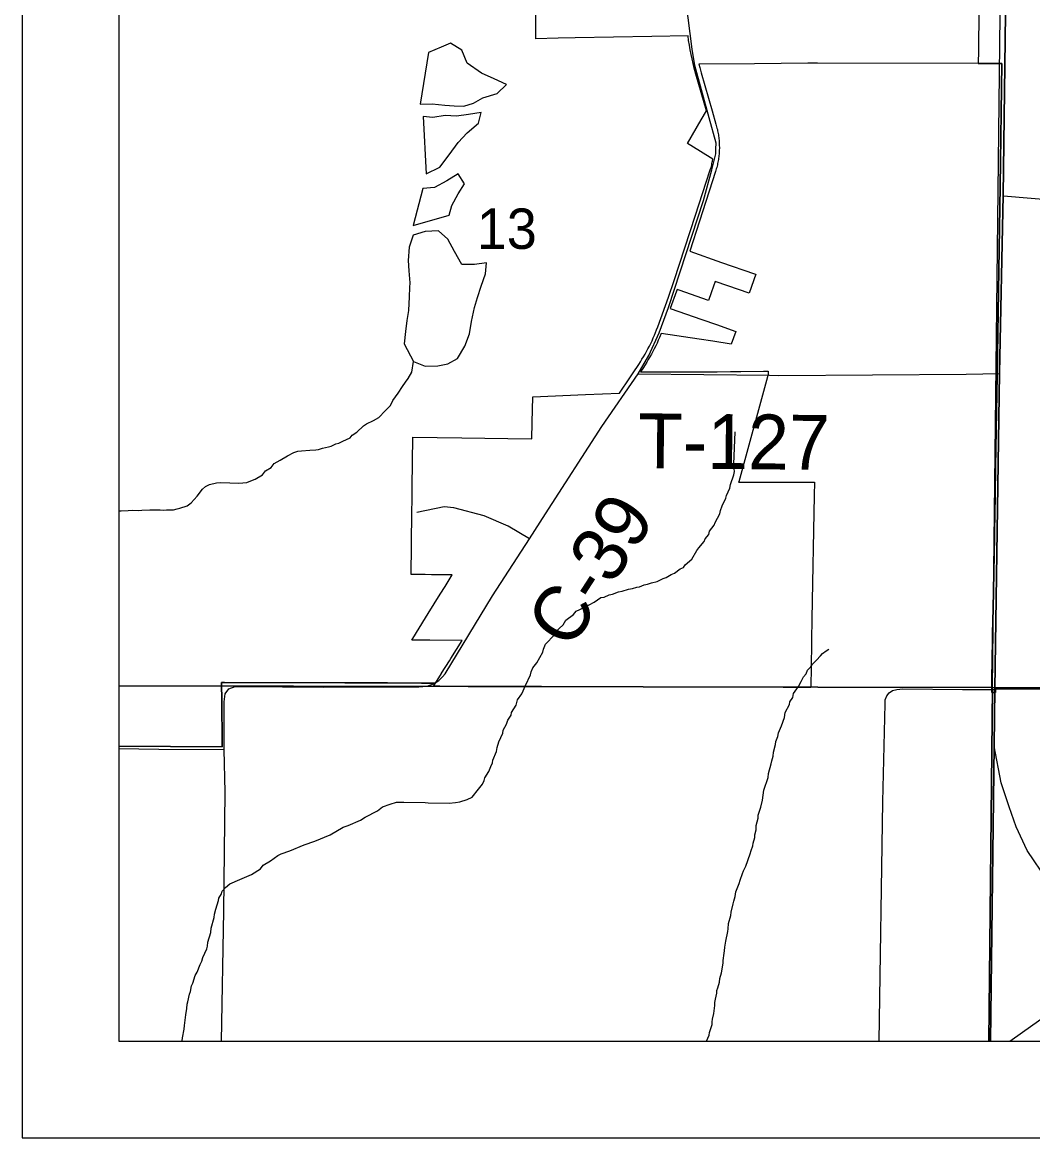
# Model space of a CAD drawing. Extents: x 0 to 34, y 0 to 22.
# Drawn here: x 2 to 3.047, y 14 to 15.156 of the extents above; entities that cross this region are included whole.
import ezdxf

# ---------------------------------------------------------------- set-up
doc = ezdxf.new("R2010")
doc.units = 0
for name, color, linetype in [('Default', 7, 'Continuous'), ('GM_X_City_Street', 7, 'Continuous'), ('GM_X_County_Road', 7, 'Continuous'), ('GM_X_County_Road_Text', 7, 'Continuous'), ('GM_X_Minor_Lake', 7, 'Continuous'), ('GM_X_Minor_River', 7, 'Continuous'), ('GM_X_Section', 7, 'Continuous'), ('GM_X_Section_Text', 7, 'Continuous'), ('GM_X_State_Route', 7, 'Continuous'), ('GM_X_Township_Road', 7, 'Continuous'), ('GM_X_Township_Road_Text', 7, 'Continuous'), ('SC_Shading3', 7, 'Continuous'), ('SH_Data', 7, 'Continuous')]:
    doc.layers.add(name, color=color, linetype=linetype)

msp = doc.modelspace()

# ---------------------------------------------------------------- linework, layer by layer
at = {"layer": 'Default'}
for points in [[(2.1, 15.4427), (2.1, 14.4681), (3.0051, 14.4664), (3.0163, 15.4353)], [(2.1, 14.4681), (2.1, 14.1), (3.0014, 14.1), (3.0051, 14.4664)], [(3.0014, 14.1), (3.9062, 14.1), (3.8976, 14.2918), (3.8947, 14.4604), (3.0051, 14.4664)]]:
    msp.add_lwpolyline(points, close=True, dxfattribs=at)
at = {"layer": 'GM_X_City_Street'}
for p, q in [((2.978, 14.791), (3.0125, 14.7916)), ((2.9742, 14.4643), (3.0076, 14.4645))]:
    msp.add_line(p, q, dxfattribs=at)
for points in [[(3.0164, 14.9758), (3.1269, 14.9664)], [(2.8876, 14.1), (2.8916, 14.3479), (2.8938, 14.4496), (2.8941, 14.4537), (2.8956, 14.4577), (2.898, 14.4609), (2.9014, 14.4634), (2.906, 14.4645), (2.9121, 14.4649), (2.9742, 14.4643)]]:
    msp.add_lwpolyline(points, dxfattribs=at)
at = {"layer": 'GM_X_County_Road'}
for points in [[(3.0165, 14.9818), (3.0224, 15.4329), (3.0236, 15.5763), (3.0235, 15.5833)], [(2.4352, 14.4775), (2.4381, 14.4807), (2.4873, 14.5614), (2.5254, 14.6205), (2.542, 14.6464), (2.6005, 14.7367), (2.6379, 14.7912), (2.6492, 14.8104), (2.6599, 14.8337), (2.6693, 14.8602), (2.7057, 14.9708), (2.7143, 15.0026), (2.7184, 15.0194), (2.7185, 15.0244), (2.7188, 15.0303), (2.7117, 15.0566), (2.6967, 15.1109), (2.6941, 15.1277), (2.6856, 15.193)], [(3.0076, 14.4645), (3.0125, 14.7916), (3.0164, 14.9758), (3.0165, 14.9818)], [(2.2064, 14.1), (2.2087, 14.2347), (2.2102, 14.358), (2.2093, 14.4023), (2.2091, 14.4514), (2.2101, 14.4598), (2.214, 14.465), (2.2205, 14.4674), (2.2268, 14.4674), (2.3125, 14.4668), (2.4108, 14.467), (2.4194, 14.4677), (2.4259, 14.4702), (2.4314, 14.4735), (2.4352, 14.4775)], [(3.1314, 14.1866), (3.0969, 14.2252), (3.062, 14.2664), (3.0411, 14.2975), (3.0297, 14.3219), (3.0224, 14.3428), (3.0142, 14.3675), (3.0069, 14.4055), (3.0076, 14.4645)]]:
    msp.add_lwpolyline(points, dxfattribs=at)
at = {"layer": 'GM_X_Minor_Lake'}
for points in [[(2.4122, 15.0708), (2.4247, 15.071), (2.4376, 15.0696), (2.4475, 15.069), (2.4574, 15.0688), (2.4674, 15.0717), (2.477, 15.0772), (2.4919, 15.0818), (2.5016, 15.0911), (2.4888, 15.0971), (2.4756, 15.1027), (2.461, 15.1132), (2.4555, 15.1266), (2.4435, 15.1341), (2.4339, 15.1297), (2.4209, 15.1243)], [(2.4209, 15.1243), (2.4122, 15.0708)], [(2.4183, 14.9985), (2.4325, 15.0055), (2.4423, 15.0182), (2.4517, 15.0309), (2.461, 15.041), (2.4727, 15.051), (2.4755, 15.062), (2.4622, 15.06), (2.45, 15.0583), (2.4382, 15.0589), (2.4252, 15.0569), (2.4153, 15.0579)], [(2.4153, 15.0579), (2.4183, 14.9985)], [(2.4422, 14.9559), (2.445, 14.9657), (2.4514, 14.9777), (2.4581, 14.9882), (2.4514, 14.9986), (2.4398, 14.9913), (2.4271, 14.9843), (2.4149, 14.9834)], [(2.4149, 14.9834), (2.405, 14.9452), (2.4422, 14.9559)], [(2.4052, 14.8042), (2.4173, 14.7994), (2.4306, 14.7995), (2.4409, 14.8016), (2.4509, 14.8071), (2.4584, 14.8199), (2.4633, 14.8327), (2.4654, 14.8456), (2.4684, 14.86), (2.4716, 14.8706), (2.4753, 14.8823), (2.4798, 14.8951), (2.4808, 14.9065), (2.4685, 14.9048), (2.4552, 14.9047), (2.4479, 14.9181), (2.4409, 14.9308), (2.4312, 14.9394), (2.4175, 14.9389), (2.4048, 14.9349), (2.4008, 14.9225), (2.3997, 14.9088), (2.4006, 14.8982), (2.4015, 14.8856)], [(2.4015, 14.8856), (2.401, 14.8807), (2.4009, 14.8712), (2.4002, 14.8571), (2.3984, 14.8465), (2.3971, 14.8351), (2.3957, 14.8226), (2.4052, 14.8042)]]:
    msp.add_lwpolyline(points, dxfattribs=at)
at = {"layer": 'GM_X_Minor_River'}
for points in [[(2.2892, 14.7117), (2.298, 14.7122), (2.3041, 14.7128), (2.3068, 14.7131), (2.311, 14.7142), (2.3172, 14.7159), (2.3199, 14.7166), (2.3249, 14.7188), (2.3279, 14.7195), (2.3322, 14.7217), (2.3395, 14.7249), (2.3419, 14.7279), (2.3465, 14.7308), (2.3536, 14.7375), (2.3567, 14.7397), (2.364, 14.743), (2.3694, 14.7463), (2.3761, 14.753), (2.3816, 14.7586), (2.384, 14.7638), (2.3895, 14.7713), (2.3939, 14.7781), (2.3971, 14.7829), (2.3998, 14.7867), (2.4034, 14.7931), (2.4052, 14.8042)], [(2.4921, 14.4044), (2.4938, 14.41), (2.4978, 14.4191), (2.4983, 14.4221), (2.5015, 14.4285), (2.5031, 14.4327), (2.5063, 14.4379), (2.5068, 14.4406), (2.5115, 14.4481), (2.5132, 14.4538), (2.5176, 14.4597), (2.5212, 14.4684), (2.5265, 14.4797), (2.5273, 14.4827), (2.5289, 14.4869), (2.5329, 14.4921), (2.5393, 14.503), (2.5401, 14.506), (2.5421, 14.5113), (2.5512, 14.521), (2.5524, 14.524), (2.5602, 14.5315), (2.563, 14.536), (2.5711, 14.5422), (2.5739, 14.5456), (2.582, 14.5492), (2.5924, 14.5547), (2.5994, 14.5595), (2.6029, 14.5601), (2.6079, 14.5623), (2.6113, 14.563), (2.6175, 14.5655), (2.6213, 14.5662), (2.6279, 14.5683), (2.6321, 14.569), (2.6367, 14.5704), (2.6394, 14.5707), (2.6444, 14.5728), (2.6478, 14.5735), (2.652, 14.5749), (2.6578, 14.5763), (2.664, 14.5792), (2.667, 14.5803), (2.6721, 14.5836), (2.6756, 14.585), (2.6814, 14.5895), (2.6849, 14.5909), (2.6868, 14.5935), (2.6935, 14.5995), (2.6987, 14.6085), (2.701, 14.6111), (2.7065, 14.6178), (2.7073, 14.6204), (2.7113, 14.6249), (2.7121, 14.6283), (2.7169, 14.6347), (2.7177, 14.6373), (2.7225, 14.6464), (2.7234, 14.6498), (2.725, 14.6547), (2.729, 14.6626), (2.7295, 14.6652), (2.7331, 14.6728), (2.7336, 14.6766), (2.7373, 14.6868), (2.7377, 14.6902), (2.7374, 14.6928), (2.7372, 14.6978), (2.7384, 14.7313)], [(2.1, 14.6496), (2.1024, 14.6495), (2.1096, 14.6497), (2.1138, 14.65), (2.1199, 14.6499), (2.1237, 14.6502), (2.1321, 14.6503), (2.1356, 14.6506), (2.1428, 14.6505), (2.1466, 14.65), (2.1493, 14.6503), (2.1565, 14.6505), (2.1604, 14.6516), (2.1631, 14.6523), (2.1707, 14.6547), (2.175, 14.6577), (2.1813, 14.6648), (2.1868, 14.6719), (2.1899, 14.6748), (2.1938, 14.6767), (2.2011, 14.6784), (2.2057, 14.6787), (2.2243, 14.6782), (2.2327, 14.6788), (2.2385, 14.6813), (2.2412, 14.6824), (2.2489, 14.6867), (2.2521, 14.6909), (2.2579, 14.6945), (2.2611, 14.6986), (2.2673, 14.7019), (2.2746, 14.7063), (2.2812, 14.71), (2.2854, 14.7114), (2.2892, 14.7117)], [(2.7391, 14.2548), (2.7427, 14.2635), (2.7436, 14.2669), (2.746, 14.2737), (2.7473, 14.2763), (2.7497, 14.2812), (2.7542, 14.294), (2.755, 14.2974), (2.7567, 14.3024), (2.7571, 14.305), (2.7588, 14.3111), (2.7589, 14.3137), (2.7602, 14.319), (2.7603, 14.3236), (2.7624, 14.3312), (2.7625, 14.3342), (2.765, 14.3425), (2.7667, 14.3497), (2.7681, 14.36), (2.7726, 14.3732), (2.7731, 14.3774), (2.7757, 14.3872), (2.7765, 14.3903), (2.7778, 14.3952), (2.7783, 14.3994), (2.7804, 14.4073), (2.7808, 14.4103), (2.7829, 14.4156), (2.7834, 14.4194), (2.7866, 14.4266), (2.7895, 14.4353), (2.7904, 14.4406), (2.7948, 14.4489), (2.7952, 14.4515), (2.7984, 14.456), (2.7989, 14.4602), (2.804, 14.4673), (2.8068, 14.4726), (2.8092, 14.4774), (2.812, 14.4804), (2.8136, 14.4842), (2.8171, 14.4879), (2.8187, 14.4905), (2.8227, 14.4946), (2.827, 14.4991), (2.8289, 14.5017), (2.8328, 14.5043), (2.8355, 14.5061)], [(2.1655, 14.1), (2.1656, 14.1002), (2.166, 14.1033), (2.1678, 14.1124), (2.1679, 14.1162), (2.1689, 14.1245), (2.1693, 14.1272), (2.1706, 14.134), (2.1707, 14.1382), (2.1716, 14.1409), (2.1733, 14.1488), (2.1741, 14.1515), (2.1754, 14.1575), (2.1766, 14.1602), (2.1791, 14.1681), (2.1811, 14.1715), (2.1844, 14.1794), (2.186, 14.1828), (2.1872, 14.1866), (2.1913, 14.1956), (2.1917, 14.1983), (2.1922, 14.2025), (2.1952, 14.2127), (2.1956, 14.2169), (2.1986, 14.2282), (2.1991, 14.2316), (2.2004, 14.2369), (2.2032, 14.2456), (2.2037, 14.2483), (2.2065, 14.2528), (2.2069, 14.2554), (2.2105, 14.2592), (2.2151, 14.2629), (2.2255, 14.2676), (2.2375, 14.2726), (2.2468, 14.2785), (2.2496, 14.2822), (2.2573, 14.287), (2.2647, 14.2925), (2.2682, 14.294), (2.277, 14.2972), (2.292, 14.3033), (2.3032, 14.3072), (2.319, 14.3137), (2.3325, 14.3217), (2.3375, 14.3235), (2.3503, 14.3289), (2.3553, 14.3319), (2.368, 14.3388), (2.3731, 14.3429), (2.3812, 14.3457), (2.3877, 14.3475), (2.3953, 14.3477), (2.4174, 14.3471), (2.4205, 14.347), (2.4422, 14.3465), (2.4487, 14.3471), (2.4533, 14.3478), (2.461, 14.3503), (2.466, 14.3528), (2.4727, 14.361), (2.4766, 14.3663), (2.4786, 14.37), (2.4791, 14.3727), (2.4835, 14.3794), (2.4855, 14.3847), (2.4871, 14.3885), (2.4876, 14.3911), (2.4912, 14.4002), (2.4921, 14.4044)], [(2.709, 14.1), (2.7116, 14.1061), (2.7121, 14.1091), (2.7146, 14.1174), (2.7146, 14.1201), (2.7151, 14.1228), (2.7164, 14.1285), (2.7173, 14.1368), (2.7174, 14.1399), (2.7183, 14.1436), (2.7196, 14.1497), (2.7197, 14.1524), (2.7205, 14.1554), (2.7222, 14.1611), (2.7226, 14.1649), (2.7243, 14.1709), (2.7261, 14.1808), (2.7262, 14.1835), (2.7271, 14.1911), (2.7276, 14.1937), (2.7277, 14.1975), (2.729, 14.2036), (2.7308, 14.2135), (2.7312, 14.2165), (2.7317, 14.2218), (2.7342, 14.2301), (2.7343, 14.2336), (2.7365, 14.2423), (2.7373, 14.2449), (2.7386, 14.2498), (2.7391, 14.2548)]]:
    msp.add_lwpolyline(points, dxfattribs=at)
at = {"layer": 'GM_X_Section'}
msp.add_lwpolyline([(3.0168, 15.4789), (4.0112, 15.46), (4.0068, 14.8003), (3.9922, 14.7706), (3.9618, 14.7034), (3.9313, 14.6142), (3.9035, 14.5261), (3.8947, 14.4604), (3.0051, 14.4664), (3.0163, 15.4353)], close=True, dxfattribs=at)
at = {"layer": 'GM_X_State_Route'}
for points in [[(2.1, 15.7155), (2.1, 14.4056), (2.2071, 14.4051), (2.2071, 14.4067), (2.2067, 14.4549), (2.2065, 14.4684), (2.2065, 14.4717), (2.2094, 14.4717), (2.3341, 14.4713), (2.3784, 14.4711), (2.4136, 14.471), (2.4171, 14.471), (2.428, 14.4709), (2.4343, 14.481), (2.4344, 14.4812), (2.4426, 14.4941), (2.444, 14.4964), (2.4556, 14.5152), (2.4222, 14.5153), (2.4035, 14.5154), (2.4085, 14.5235), (2.4205, 14.5429), (2.433, 14.563), (2.438, 14.5712), (2.4453, 14.583), (2.4423, 14.5831), (2.424, 14.5833), (2.4175, 14.5834), (2.4028, 14.5836), (2.4032, 14.6135), (2.4037, 14.6499), (2.4038, 14.6593), (2.404, 14.6741), (2.4047, 14.7256), (2.4299, 14.7253), (2.4552, 14.7249), (2.5029, 14.7243), (2.5278, 14.724), (2.5282, 14.741), (2.5288, 14.7677), (2.5834, 14.7699), (2.6186, 14.7713), (2.6293, 14.7873), (2.6315, 14.7905), (2.6327, 14.7924), (2.6387, 14.8012), (2.6404, 14.8038), (2.642, 14.8064), (2.6437, 14.8091), (2.6452, 14.8117), (2.6467, 14.8144), (2.6482, 14.8171), (2.6497, 14.8201), (2.6511, 14.8229), (2.6524, 14.8257), (2.6537, 14.8285), (2.6549, 14.8313), (2.6561, 14.8342), (2.6572, 14.8371), (2.6584, 14.8402), (2.6694, 14.8707), (2.6755, 14.8879), (2.6976, 14.9558), (2.7048, 14.9781), (2.7128, 15.0028), (2.7136, 15.0053), (2.7139, 15.0066), (2.7142, 15.0079), (2.7145, 15.0092), (2.7148, 15.0105), (2.7151, 15.0118), (2.7155, 15.0139), (2.6927, 15.0278), (2.6891, 15.03), (2.7034, 15.0545), (2.7088, 15.0637), (2.6979, 15.1017), (2.6962, 15.1082), (2.695, 15.1129), (2.6939, 15.1176), (2.6929, 15.1223), (2.6919, 15.1271), (2.6911, 15.1319), (2.6903, 15.1366), (2.6897, 15.1414), (2.6522, 15.1408), (2.5728, 15.1393), (2.5553, 15.139), (2.532, 15.1386), (2.5319, 15.1867)], [(2.9911, 15.1676), (2.9905, 15.1263), (2.9903, 15.113), (3.0086, 15.113), (3.0149, 15.113), (3.013, 14.9859), (3.0101, 14.7895), (3.0084, 14.695), (3.0079, 14.6653), (3.0072, 14.6277), (3.0071, 14.6225), (3.0065, 14.5851), (3.0058, 14.5482), (3.0053, 14.5225), (3.0052, 14.5141), (3.0049, 14.4971), (3.0045, 14.4737), (3.0044, 14.4688), (3.0043, 14.4613), (3.0081, 14.4612), (3.0081, 14.4614), (3.0081, 14.465), (3.0085, 14.465), (3.0119, 14.465), (3.0166, 14.465), (3.0176, 14.465), (3.0299, 14.465), (3.0327, 14.465), (3.0419, 14.4649), (3.046, 14.4649), (3.0554, 14.4649)]]:
    msp.add_lwpolyline(points, dxfattribs=at)
at = {"layer": 'GM_X_Township_Road'}
msp.add_line((2.6379, 14.7912), (2.774, 14.7899), dxfattribs=at)
for points in [[(2.1, 17.494), (2.1, 14.1), (3.0031, 14.1), (3.0067, 14.4061), (3.0074, 14.465), (3.0123, 14.7921), (3.0162, 14.9764), (3.0222, 15.4334), (3.0233, 15.5768), (3.0198, 16.3586)], [(3.0198, 16.3586), (3.0233, 15.5768), (3.0222, 15.4334), (3.0162, 14.9764), (3.0123, 14.7921), (3.0074, 14.465), (3.0067, 14.4061), (3.0031, 14.1), (3.9251, 14.1)], [(2.774, 14.7899), (2.7837, 14.7898), (2.978, 14.791)], [(2.5254, 14.6205), (2.5032, 14.6335), (2.4784, 14.6441), (2.4471, 14.6526), (2.4369, 14.6536), (2.4086, 14.6476)], [(2.1, 14.4031), (2.1413, 14.4024), (2.2093, 14.4023)], [(3.0232, 14.1), (3.0363, 14.1092), (3.0671, 14.1311), (3.0828, 14.1429), (3.1007, 14.1583), (3.1314, 14.1866)]]:
    msp.add_lwpolyline(points, dxfattribs=at)
at = {"layer": 'SC_Shading3'}
msp.add_lwpolyline([(3.0554, 14.4649), (3.046, 14.4649), (3.0431, 14.4649), (3.0419, 14.4649), (3.0327, 14.465), (3.0299, 14.465), (3.0176, 14.465), (3.0166, 14.465), (3.0119, 14.465), (3.0085, 14.465), (3.0081, 14.465), (3.0081, 14.4614), (3.0081, 14.4612), (3.0043, 14.4613), (3.0044, 14.4688), (3.0045, 14.4737), (3.0049, 14.4971), (3.0052, 14.5141), (3.0053, 14.5225), (3.0058, 14.5482), (3.0065, 14.5851), (3.0071, 14.6225), (3.0072, 14.6277), (3.0079, 14.6653), (3.0084, 14.695), (3.0101, 14.7895), (3.013, 14.9859), (3.0149, 15.113), (3.0086, 15.113), (2.9903, 15.113), (2.8239, 15.1132), (2.8232, 15.1132), (2.8137, 15.1131), (2.7587, 15.1126), (2.701, 15.1121), (2.7019, 15.1086), (2.7034, 15.1033), (2.7146, 15.064), (2.7186, 15.05), (2.719, 15.0485), (2.7197, 15.0459), (2.7201, 15.0445), (2.7204, 15.0432), (2.7207, 15.0418), (2.7209, 15.0404), (2.7212, 15.039), (2.7214, 15.0376), (2.7215, 15.0362), (2.7217, 15.0347), (2.7218, 15.0333), (2.722, 15.0319), (2.722, 15.0305), (2.7221, 15.0291), (2.7221, 15.0276), (2.7222, 15.0262), (2.7222, 15.0248), (2.7221, 15.0234), (2.7221, 15.022), (2.722, 15.0205), (2.7219, 15.0191), (2.7217, 15.0177), (2.7216, 15.0163), (2.7214, 15.0149), (2.7212, 15.0135), (2.7209, 15.0121), (2.7207, 15.0107), (2.7204, 15.0093), (2.7201, 15.0079), (2.7198, 15.0065), (2.7194, 15.0051), (2.719, 15.0038), (2.7186, 15.0024), (2.7182, 15.0011), (2.7015, 14.9496), (2.6914, 14.9183), (2.7245, 14.9068), (2.7584, 14.8951), (2.76, 14.8945), (2.7531, 14.8748), (2.7309, 14.8825), (2.7177, 14.8871), (2.716, 14.8821), (2.7136, 14.8752), (2.7109, 14.8675), (2.6805, 14.878), (2.6783, 14.8788), (2.6776, 14.877), (2.6712, 14.8592), (2.704, 14.8478), (2.7193, 14.8424), (2.7394, 14.8354), (2.7344, 14.8221), (2.7153, 14.8251), (2.7014, 14.8272), (2.6619, 14.8333), (2.6602, 14.8291), (2.6589, 14.8262), (2.6576, 14.8233), (2.6562, 14.8204), (2.6547, 14.8173), (2.6532, 14.8145), (2.6517, 14.8117), (2.6501, 14.8089), (2.6485, 14.8061), (2.6469, 14.8034), (2.6452, 14.8007), (2.6434, 14.7981), (2.6403, 14.7935), (2.7198, 14.7935), (2.7336, 14.7937), (2.7444, 14.7938), (2.7679, 14.7941), (2.7728, 14.7941), (2.7728, 14.7913), (2.7721, 14.7884), (2.7422, 14.6796), (2.742, 14.6791), (2.8206, 14.6791), (2.8204, 14.6653), (2.8197, 14.6291), (2.8188, 14.5746), (2.8181, 14.5374), (2.8177, 14.5154), (2.8172, 14.485), (2.817, 14.4697), (2.8169, 14.4664), (2.8026, 14.4664), (2.7883, 14.4665), (2.7453, 14.4667), (2.7193, 14.4667), (2.7034, 14.4668), (2.6962, 14.4668), (2.6008, 14.4672), (2.538, 14.4674), (2.5237, 14.4675), (2.5158, 14.4675), (2.493, 14.4676), (2.4327, 14.4678), (2.4278, 14.4678), (2.426, 14.4678), (2.4263, 14.4682), (2.428, 14.4709), (2.4265, 14.4709), (2.4171, 14.471), (2.4136, 14.471), (2.3784, 14.4711), (2.3341, 14.4713), (2.2094, 14.4717), (2.2065, 14.4717), (2.2065, 14.4684), (2.2067, 14.4549), (2.2071, 14.4067), (2.2071, 14.4051), (2.1, 14.4056), (2.1, 14.1), (5.103, 14.1)], dxfattribs=at)
at = {"layer": 'SH_Data'}
for p, q in [((2, 21), (2, 14)), ((2.1, 20.9), (2.1, 14.1)), ((2.1, 14.1), (8.9, 14.1)), ((2.1, 14.1), (2.1, 14.1)), ((2, 14), (9, 14))]:
    msp.add_line(p, q, dxfattribs=at)

# ---------------------------------------------------------------- texts
at = {"layer": 'GM_X_County_Road_Text'}
msp.add_text('C-39', height=0.05682, rotation=57.1434, dxfattribs=at).set_placement((2.5675, 14.5038))
at = {"layer": 'GM_X_Section_Text'}
msp.add_text('13', height=0.04186, rotation=0, dxfattribs=at).set_placement((2.4708, 14.9208))
at = {"layer": 'GM_X_Township_Road_Text'}
msp.add_text('T-127', height=0.05682, rotation=359.4386, dxfattribs=at).set_placement((2.6377, 14.6937))

doc.saveas('drawing.dxf')
